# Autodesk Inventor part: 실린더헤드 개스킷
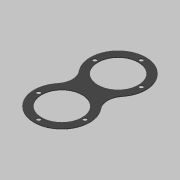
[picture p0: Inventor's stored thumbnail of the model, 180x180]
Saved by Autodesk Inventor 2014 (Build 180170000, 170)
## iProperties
Created: 2019-08
Part Number: 실린더헤드 개스킷
Material: 고무
Document SubType Name: Modeling
Designer: mduedu
Density: 0.93 g/cm^3
Appearance: 고무 - 검은색 - 버전 1.1
Mass: 5.11044 g
Surface Area: 119.346 cm^2
Volume: 5.49509 cm^3
Author: mduedu
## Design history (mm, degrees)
sketch "스케치1"
  geometry: L1 (0, 0)-(0, 85); C1 r 30.5 at (0, 85); C2 r 30.5 at (0, 0); A1 r 42 centre (0, 0) between (0, 42) and (-32.469, 26.642); A2 r 42 centre (0, 85) between (0, 43) and (32.469, 58.358); A3 r 25 centre (51.795, 42.5) between (32.469, 58.358) and (32.469, 26.642); A4 r 25 centre (-51.795, 42.5) between (-32.469, 26.642) and (-32.469, 58.358); A5 r 42 centre (0, 0) between (32.469, 26.642) and (0, 42); A6 r 42 centre (0, 0) between (-32.469, 26.642) and (32.469, 26.642); A7 r 42 centre (0, 85) between (-32.469, 58.358) and (0, 43); A8 r 42 centre (0, 85) between (32.469, 58.358) and (-32.469, 58.358); A9 r 25 centre (51.795, 42.5) between (32.469, 26.642) and (32.469, 58.358); A10 r 25 centre (-51.795, 42.5) between (-32.469, 58.358) and (-32.469, 26.642); 1 further point
  constraints: 20 point on circle, 12 centre point, 4 coincident, 4 tangent, 2 end point, 2 point on line, 1 vertical
  dimensions: "d1" = 84 diameter of A1; "d3" = 85 distance of L1.start L1.end; "d4" = 84 diameter of A2; "d5" = 50 diameter of A3; "d6" = 50 diameter of A4 (= d5); "d11" = 61 diameter of C1; "d12" = 61 diameter of C2
extrude "돌출2" new body sketch "스케치1" distance "d13" = 1; taper "d14" = 0 deg
sketch "스케치2"
  geometry: A1 r 35 centre (0, 0) between (-35, 0) and (0, 35); 2 further points
  constraints: 3 point on circle, 2 horizontal alignment, 1 centre point, 1 coincident, 1 vertical alignment
  dimensions: "d15" = 70 diameter of A1
hole "구멍1" sketch "스케치2" at (-35, 0), (0, 35), (35, 0) diameter "d16" = 6; stored, may be unused: countersink angle "d20" = 90 deg, drill point angle "d22" = 118 deg; dims "d17" = 6, "d18" = 4, "d19" = 2, "d21" = 8
node "작업 평면1"
mirror "대칭1"
node "솔리드2"
other parameters: "d23" = 42.5
